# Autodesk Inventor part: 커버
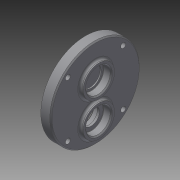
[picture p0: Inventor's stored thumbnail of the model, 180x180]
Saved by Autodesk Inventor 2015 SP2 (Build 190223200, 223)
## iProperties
Created: 2015-06
Part Number: 커버
Material: 일반
Document SubType Name: Modeling
Designer: AMC
Density: 1 g/cm^3
Appearance: 기본값
Author: AMC
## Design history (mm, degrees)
sketch "스케치1"
  geometry: C1 r 40 at (0, 0); 1 further point
  constraints: 1 centre point, 1 coincident
  dimensions: "d0" = 80 diameter of C1
extrude "돌출1" new body sketch "스케치1" distance "d1" = 9; taper "d2" = 0 deg
sketch "스케치2"
  geometry: C1 r 16 at (-20, 0); 1 further point
  constraints: 1 centre point, 1 horizontal alignment
  dimensions: "d3" = 20 distance of point (0, 0) C1.centre; "d4" = 32 diameter of C1
extrude "돌출2" join sketch "스케치2" distance "d5" = 4; taper "d6" = 0 deg
sketch "스케치3"
  geometry: C1 r 14 at (-11, 0); C2 r 14 at (20, 0); 1 further point
  constraints: 2 centre point, 2 horizontal alignment
  dimensions: "d7" = 28 diameter of C1; "d8" = 28 diameter of C2; "d9" = 11 distance of C1.centre point (0, 0); "d10" = 20 distance of point (0, 0) C2.centre
extrude "돌출3" join sketch "스케치3" distance "d11" = 3; taper "d12" = 0 deg
chamfer "모따기1" distance "d13" = 1; stored, may be unused: second distance "d14" = 2, angle "d15" = 45 deg
sketch "스케치4"
  geometry: L1 (9, -4)-(13, -4) reference; L2 (13, -4)-(13, -36) reference; L3 (13, -36)-(9, -36) reference; L4 (9, -36)-(9, -40) reference; L5 (9, -40)-(1, -40) reference; L6 (1, -40)-(0, -39) reference; L7 (0, -39)-(0, -34) reference; L8 (0, -34)-(-3, -34) reference; L9 (-3, -34)-(-3, -6) reference; L10 (-3, -6)-(0, -6) reference; L11 (0, -6)-(0, -3) reference; L12 (0, -3)-(-3, -3) reference; L13 (-3, -3)-(-3, 25) reference; L14 (-3, 25)-(0, 25) reference; L15 (0, 25)-(0, 39) reference; L16 (0, 39)-(1, 40) reference; L17 (1, 40)-(9, 40) reference; L18 (9, 40)-(9, -4) reference; L19 (13, -36)-(13, -4) reference; L20 (13, -20)-(-3, -20); L21 (-3, 25)-(-3, -3) reference; L22 (-3, 11)-(9, 11); L23 (-3, 11)-(-3, 22); L24 (-3, 22)-(4, 22); L25 (4, 22)-(4, 20); L26 (4, 20)-(5, 20); L27 (5, 20)-(5, 11); L28 (13, -20)-(13, -9); L29 (13, -9)-(6, -9); L30 (6, -9)-(6, -12.5); L31 (6, -12.5)-(4, -12.5); L32 (4, -12.5)-(4, -9); L33 (4, -9)-(-3, -9); L34 (-3, -20)-(-3, -9); 1 further point
  constraints: 28 end point, 5 point on line, 3 midpoint, 1 vertical
  dimensions: "d16" = 11 distance from line of L22 point (0, 0); "d17" = 22 diameter of L29 L20; "d18" = 22 diameter of L33 L20; "d19" = 15 diameter of L31 L20; "d20" = 7 distance of L28.end L29.end; "d21" = 7 distance of L32.end L33.end; "d22" = 2 distance of L30.end L31.end; "d23" = 3.5 distance of L29.end L30.end; "d24" = 1 distance of L25.end L26.end; "d25" = 7 distance of L23.end L24.end; "d26" = 22 diameter of L24 L22; "d27" = 18 diameter of L26 L22; "d28" = 2 distance of L24.end L25.end
  node "절단 모서리 투영1"
revolve "회전1" stored, may be unused: angle "d29" = 90 deg
revolve "회전2" stored, may be unused: angle "d30" = 90 deg
fillet "모깎기1" dims "d31" = 0.3
chamfer "모따기2" distance "d32" = 1; stored, may be unused: second distance "d33" = 2, angle "d34" = 45 deg
fillet "모깎기2" dims "d35" = 2
sketch "스케치6"
  geometry: L1 (0, 0)-(-24.749, 24.749); L2 (0, 0)-(35, 0); C1 r 35 at (0, 0); 2 further points
  constraints: 4 end point, 2 coincident, 1 centre point, 1 equal length, 1 horizontal
  dimensions: "d41" = 70 diameter of C1; "d42" = 35 distance of L1.start L1.end; "d43" = 135 deg angle of L2 L1
hole "구멍1" sketch "스케치6" at (-24.749, 24.749) diameter "d44" = 4.5; stored, may be unused: countersink angle "d48" = 90 deg, drill point angle "d50" = 118 deg; dims "d45" = 6, "d46" = 8, "d47" = 4.4, "d49" = 8
node "솔리드1"
pattern_circular "원형 패턴1" dims angle "d52" = 360 deg
